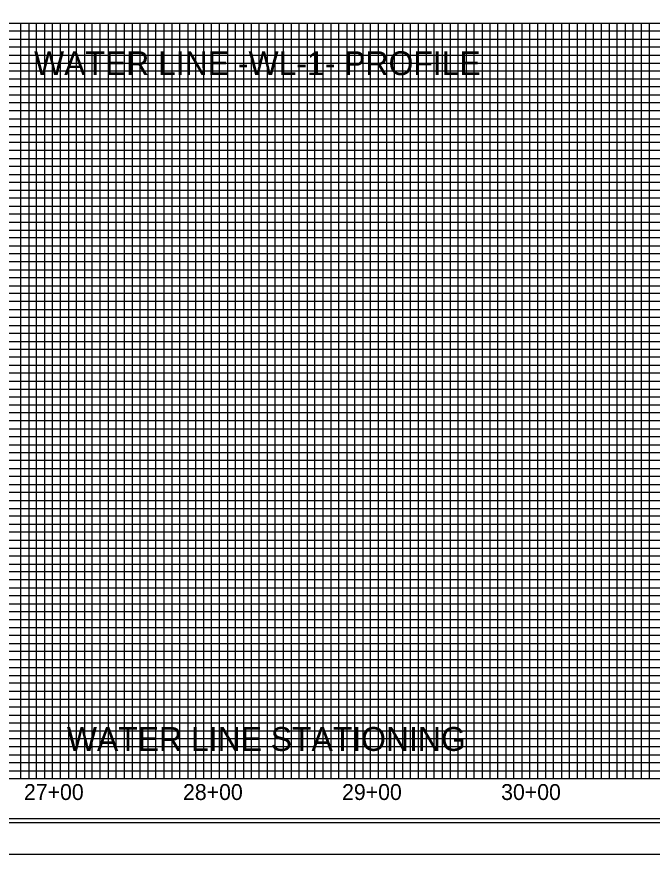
# Model space of a CAD drawing. Extents: x 0 to 2694, y -1 to 1501.
# Drawn here: x 1.351 to 2.017, y 0.008 to 0.886 of the extents above; entities that cross this region are included whole.
import ezdxf

# ---------------------------------------------------------------- set-up
doc = ezdxf.new("R2010")
doc.units = 0
for name, color, linetype in [('11 x 17 Ledger Page CELL', 7, 'Continuous'), ('Air Release (B1) CELL', 7, 'Continuous'), ('COGO Default Point Elevation', 7, 'Continuous'), ('Exist Utilities Sanitary Sewer Clean-Out CELL', 7, 'Continuous'), ('P_UTL_Water', 7, 'Continuous')]:
    doc.layers.add(name, color=color, linetype=linetype)

msp = doc.modelspace()

# ---------------------------------------------------------------- linework, layer by layer
at = {"layer": '11 x 17 Ledger Page CELL'}
for p, q in [((0.30499, 0.8375), (2.59666, 0.8375)), ((2.80499, 0.75416), (0.30499, 0.75416)), ((0.30499, 0.67083), (2.80499, 0.67083)), ((2.80499, 0.5875), (0.30499, 0.5875)), ((0.30499, 0.50416), (2.80499, 0.50416)), ((2.80499, 0.42083), (0.30499, 0.42083)), ((0.30499, 0.3375), (2.80499, 0.3375)), ((2.80499, 0.25416), (0.30499, 0.25416)), ((0.30499, 0.17083), (2.80499, 0.17083))]:
    msp.add_line(p, q, dxfattribs=at)
for points in [[(1.42999, 0.0875), (1.42999, 0.87916), (1.51333, 0.87916), (1.51333, 0.0875)], [(1.59666, 0.0875), (1.59666, 0.87916), (1.67999, 0.87916), (1.67999, 0.0875)], [(1.76333, 0.0875), (1.76333, 0.87916), (1.84666, 0.87916), (1.84666, 0.0875)], [(1.92999, 0.0875), (1.92999, 0.87916), (2.01333, 0.87916), (2.01333, 0.0875)]]:
    msp.add_lwpolyline(points, dxfattribs=at)
at = {"layer": 'COGO Default Point Elevation'}
msp.add_line((2.80499, 0.0875), (0.30499, 0.0875), dxfattribs=at)
for points in [[(0.02749, 0.00833), (2.83333, 0.00833), (2.83333, 1.83333), (0.02749, 1.83333)], [(0.04916, 0.04166), (2.82583, 0.04166), (2.82583, 1.8), (0.04916, 1.8)], [(2.80499, 1.79583), (0.30499, 1.79583), (0.30499, 0.04583), (2.80499, 0.04583)], [(0.38833, 0.87916), (2.59666, 0.87916), (2.59666, 0.79583), (2.72166, 0.79583), (2.72166, 0.0875), (0.38833, 0.0875)]]:
    msp.add_lwpolyline(points, close=True, dxfattribs=at)
at = {"layer": 'Exist Utilities Sanitary Sewer Clean-Out CELL'}
for points in [[(1.35499, 0.0875), (1.35499, 0.87916), (1.36333, 0.87916), (1.36333, 0.0875)], [(1.37166, 0.0875), (1.37166, 0.87916), (1.37999, 0.87916), (1.37999, 0.0875)], [(1.39666, 0.0875), (1.39666, 0.87916), (1.40499, 0.87916), (1.40499, 0.0875)], [(1.41333, 0.0875), (1.41333, 0.87916), (1.42166, 0.87916), (1.42166, 0.0875)], [(1.43833, 0.0875), (1.43833, 0.87916), (1.44666, 0.87916), (1.44666, 0.0875)], [(1.45499, 0.0875), (1.45499, 0.87916), (1.46333, 0.87916), (1.46333, 0.0875)], [(1.47999, 0.0875), (1.47999, 0.87916), (1.48833, 0.87916), (1.48833, 0.0875)], [(1.49666, 0.0875), (1.49666, 0.87916), (1.50499, 0.87916), (1.50499, 0.0875)], [(1.52166, 0.0875), (1.52166, 0.87916), (1.52999, 0.87916), (1.52999, 0.0875)], [(1.53833, 0.0875), (1.53833, 0.87916), (1.54666, 0.87916), (1.54666, 0.0875)], [(1.56333, 0.0875), (1.56333, 0.87916), (1.57166, 0.87916), (1.57166, 0.0875)], [(1.57999, 0.0875), (1.57999, 0.87916), (1.58833, 0.87916), (1.58833, 0.0875)], [(1.60499, 0.0875), (1.60499, 0.87916), (1.61333, 0.87916), (1.61333, 0.0875)], [(1.62166, 0.0875), (1.62166, 0.87916), (1.62999, 0.87916), (1.62999, 0.0875)], [(1.64666, 0.0875), (1.64666, 0.87916), (1.65499, 0.87916), (1.65499, 0.0875)], [(1.66333, 0.0875), (1.66333, 0.87916), (1.67166, 0.87916), (1.67166, 0.0875)], [(1.68833, 0.0875), (1.68833, 0.87916), (1.69666, 0.87916), (1.69666, 0.0875)], [(1.70499, 0.0875), (1.70499, 0.87916), (1.71333, 0.87916), (1.71333, 0.0875)], [(1.72999, 0.0875), (1.72999, 0.87916), (1.73833, 0.87916), (1.73833, 0.0875)], [(1.74666, 0.0875), (1.74666, 0.87916), (1.75499, 0.87916), (1.75499, 0.0875)], [(1.77166, 0.0875), (1.77166, 0.87916), (1.77999, 0.87916), (1.77999, 0.0875)], [(1.78833, 0.0875), (1.78833, 0.87916), (1.79666, 0.87916), (1.79666, 0.0875)], [(1.81333, 0.0875), (1.81333, 0.87916), (1.82166, 0.87916), (1.82166, 0.0875)], [(1.82999, 0.0875), (1.82999, 0.87916), (1.83833, 0.87916), (1.83833, 0.0875)], [(1.85499, 0.0875), (1.85499, 0.87916), (1.86333, 0.87916), (1.86333, 0.0875)], [(1.87166, 0.0875), (1.87166, 0.87916), (1.87999, 0.87916), (1.87999, 0.0875)], [(1.89666, 0.0875), (1.89666, 0.87916), (1.90499, 0.87916), (1.90499, 0.0875)], [(1.91333, 0.0875), (1.91333, 0.87916), (1.92166, 0.87916), (1.92166, 0.0875)], [(1.93833, 0.0875), (1.93833, 0.87916), (1.94666, 0.87916), (1.94666, 0.0875)], [(1.95499, 0.0875), (1.95499, 0.87916), (1.96333, 0.87916), (1.96333, 0.0875)], [(1.97999, 0.0875), (1.97999, 0.87916), (1.98833, 0.87916), (1.98833, 0.0875)], [(1.99666, 0.0875), (1.99666, 0.87916), (2.00499, 0.87916), (2.00499, 0.0875)], [(0.38833, 0.8625), (2.59666, 0.8625), (2.59666, 0.87083), (0.38833, 0.87083)], [(0.38833, 0.84583), (2.59666, 0.84583), (2.59666, 0.85416), (0.38833, 0.85416)], [(0.38833, 0.82083), (2.59666, 0.82083), (2.59666, 0.82916), (0.38833, 0.82916)], [(0.38833, 0.80416), (2.59666, 0.80416), (2.59666, 0.8125), (0.38833, 0.8125)], [(0.38833, 0.77916), (2.72166, 0.77916), (2.72166, 0.7875), (0.38833, 0.7875)], [(0.38833, 0.7625), (2.72166, 0.7625), (2.72166, 0.77083), (0.38833, 0.77083)], [(0.38833, 0.7375), (2.72166, 0.7375), (2.72166, 0.74583), (0.38833, 0.74583)], [(0.38833, 0.72083), (2.72166, 0.72083), (2.72166, 0.72916), (0.38833, 0.72916)], [(0.38833, 0.70416), (2.72166, 0.70416)], [(0.38833, 0.6875), (2.72166, 0.6875), (2.72166, 0.69583), (0.38833, 0.69583)], [(0.38833, 0.6625), (2.72166, 0.6625), (2.72166, 0.67916), (0.38833, 0.67916)], [(0.38833, 0.64583), (2.72166, 0.64583), (2.72166, 0.65416), (0.38833, 0.65416)], [(0.38833, 0.62083), (2.72166, 0.62083), (2.72166, 0.6375), (0.38833, 0.6375)], [(0.38833, 0.60416), (2.72166, 0.60416), (2.72166, 0.6125), (0.38833, 0.6125)], [(0.38833, 0.57916), (2.72166, 0.57916), (2.72166, 0.59583), (0.38833, 0.59583)], [(0.38833, 0.5625), (2.72166, 0.5625), (2.72166, 0.57083), (0.38833, 0.57083)], [(0.38833, 0.5375), (2.72166, 0.5375), (2.72166, 0.55416), (0.38833, 0.55416)], [(0.38833, 0.52083), (2.72166, 0.52083), (2.72166, 0.52916), (0.38833, 0.52916)], [(0.38833, 0.49583), (2.72166, 0.49583), (2.72166, 0.5125), (0.38833, 0.5125)], [(0.38833, 0.47916), (2.72166, 0.47916), (2.72166, 0.4875), (0.38833, 0.4875)], [(0.38833, 0.45416), (2.72166, 0.45416), (2.72166, 0.47083), (0.38833, 0.47083)], [(0.38833, 0.4375), (2.72166, 0.4375), (2.72166, 0.44583), (0.38833, 0.44583)], [(0.38833, 0.4125), (2.72166, 0.4125), (2.72166, 0.42916), (0.38833, 0.42916)], [(0.38833, 0.39583), (2.72166, 0.39583), (2.72166, 0.40416), (0.38833, 0.40416)], [(0.38833, 0.37083), (2.72166, 0.37083), (2.72166, 0.3875), (0.38833, 0.3875)], [(0.38833, 0.35416), (2.72166, 0.35416), (2.72166, 0.3625), (0.38833, 0.3625)], [(0.38833, 0.32916), (2.72166, 0.32916), (2.72166, 0.34583), (0.38833, 0.34583)], [(0.38833, 0.3125), (2.72166, 0.3125), (2.72166, 0.32083), (0.38833, 0.32083)], [(0.38833, 0.2875), (2.72166, 0.2875), (2.72166, 0.30416), (0.38833, 0.30416)], [(0.38833, 0.27083), (2.72166, 0.27083), (2.72166, 0.27916), (0.38833, 0.27916)], [(0.38833, 0.24583), (2.72166, 0.24583), (2.72166, 0.2625), (0.38833, 0.2625)], [(0.38833, 0.22916), (2.72166, 0.22916), (2.72166, 0.2375), (0.38833, 0.2375)], [(0.38833, 0.20416), (2.72166, 0.20416), (2.72166, 0.22083), (0.38833, 0.22083)], [(0.38833, 0.09583), (2.72166, 0.09583), (2.72166, 0.10416), (0.38833, 0.10416), (0.38833, 0.1125), (2.72166, 0.1125), (2.72166, 0.12083), (0.38833, 0.12083), (0.38833, 0.12916), (0.38833, 0.1375), (2.72166, 0.1375), (2.72166, 0.14583), (0.38833, 0.14583), (0.38833, 0.15416), (2.72166, 0.15416), (2.72166, 0.1625), (0.38833, 0.1625), (0.38833, 0.17083), (0.38833, 0.17916), (2.72166, 0.17916), (2.72166, 0.1875), (0.38833, 0.1875), (0.38833, 0.19583), (2.72166, 0.19583)]]:
    msp.add_lwpolyline(points, dxfattribs=at)
at = {"layer": 'P_UTL_Water'}
for points in [[(0.30499, 0.87916), (2.59666, 0.87916)], [(1.38833, 0.0875), (1.38833, 0.87916), (1.47166, 0.87916), (1.47166, 0.0875)], [(1.55499, 0.0875), (1.55499, 0.87916), (1.63833, 0.87916), (1.63833, 0.0875)], [(1.72166, 0.0875), (1.72166, 0.87916), (1.80499, 0.87916), (1.80499, 0.0875)], [(1.88833, 0.0875), (1.88833, 0.87916), (1.97166, 0.87916), (1.97166, 0.0875)], [(2.80499, 0.79583), (0.30499, 0.79583), (0.30499, 0.7125), (2.80499, 0.7125)], [(2.80499, 0.62916), (0.30499, 0.62916), (0.30499, 0.54583), (2.80499, 0.54583)], [(2.80499, 0.4625), (0.30499, 0.4625), (0.30499, 0.37916), (2.80499, 0.37916)], [(2.80499, 0.29583), (0.30499, 0.29583), (0.30499, 0.2125), (2.80499, 0.2125)], [(2.80499, 0.12916), (0.30499, 0.12916)]]:
    msp.add_lwpolyline(points, dxfattribs=at)

# ---------------------------------------------------------------- texts
at = {"layer": 'Air Release (B1) CELL'}
for s, p in [('WATER LINE -WL-1- PROFILE', (1.36895, 0.82485)), ('WATER LINE STATIONING', (1.40335, 0.11664))]:
    msp.add_text(s, height=0.025, dxfattribs=at).set_placement(p)
at = {"layer": 'COGO Default Point Elevation'}
for s, p in [('27+00', (1.35837, 0.06519)), ('28+00', (1.52503, 0.06519)), ('29+00', (1.6917, 0.06519)), ('30+00', (1.85837, 0.06519))]:
    msp.add_text(s, height=0.016667, dxfattribs=at).set_placement(p)

doc.saveas('drawing.dxf')
